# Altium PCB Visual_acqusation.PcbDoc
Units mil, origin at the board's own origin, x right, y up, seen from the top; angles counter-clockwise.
Board outline 1181.1 x 1968.5 mil, 2 copper layers (Top Layer, Bottom Layer), stack 65.792 mil thick; 39 components, 21 nets, 119 pads, 35 vias.
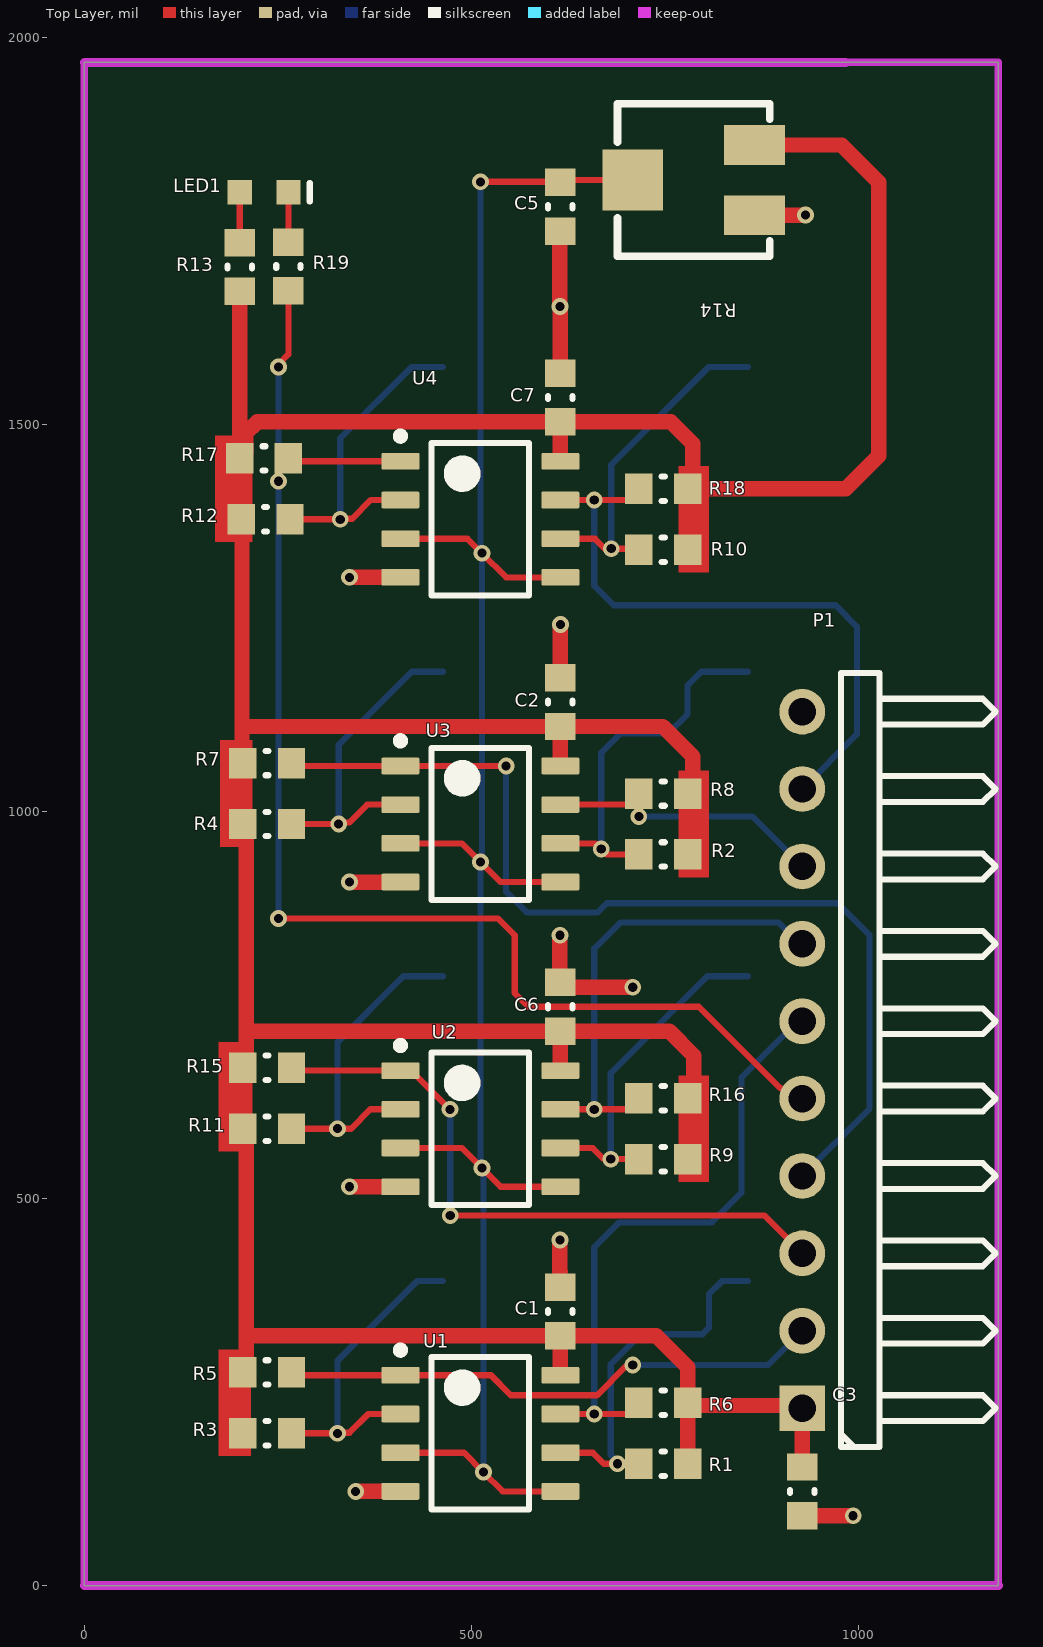
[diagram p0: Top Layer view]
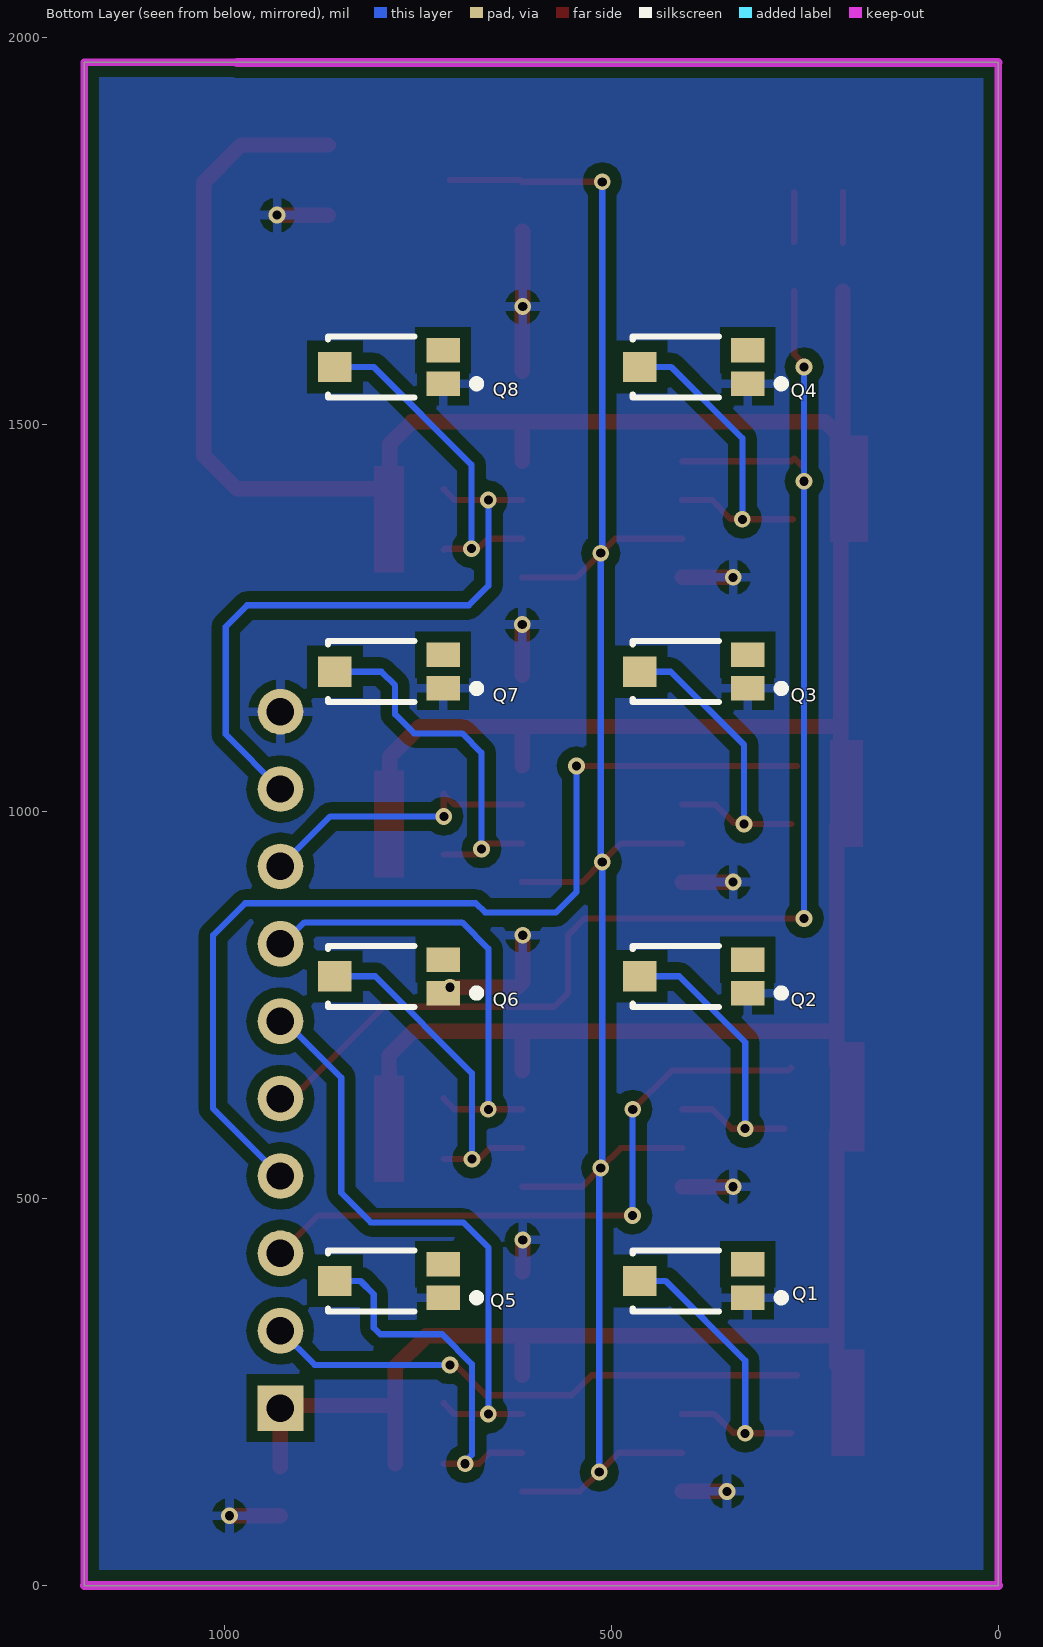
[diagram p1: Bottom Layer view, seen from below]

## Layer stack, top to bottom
Top Solder: solder mask 0.4, Solder Resist, Dk 3.5
Top Layer: signal copper 1.4
Dielectric1: core 62.9921, FR-4, Dk 4.8
Bottom Layer: signal copper 1.4
Bottom Solder: solder mask 0.4, Solder Resist, Dk 3.5

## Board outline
0,0 1181.1,0 1181.1,1968.5 0,1968.5

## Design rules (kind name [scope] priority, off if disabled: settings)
Clearance Clearance_1 [InPolygon] p1: gap=14 ignorepadtopadclearanceinfootprint=FALSE except(0: Arc-Hole Track-Hole SMDPad-Hole THPad-Hole Via-Hole Fill-Hole Poly-Hole Region-Hole Text-Hole)
Clearance [All] p2: gap=6 ignorepadtopadclearanceinfootprint=FALSE except(0: Arc-Hole Track-Hole SMDPad-Hole THPad-Hole Via-Hole Fill-Hole Poly-Hole Region-Hole Text-Hole)
FabricationTestPointUsage TestPointUsage [All] p1: valid=0 allowmultiple=FALSE
FabricationTestpoint Testpoint [(IsPad And (OnTopLayer Or OnBottomLayer))] p1: side=3 testpointundercomponent=TRUE minsize=40 maxsize=100 preferedsize=60 minholesize=0 maxholesize=40 preferedholesize=32 testpointgrid=1 allowsidetop=TRUE allowsidebottom=TRUE usegrid=TRUE gridtolerance=0.01
HoleSize [All] p1: absolutevalues=TRUE maxlimit=787.4 minlimit=11.81 maxpercent=80.000 minpercent=20.000
HoleToHoleClearance [All] p1: gap=0 allowstackedmicrovias=TRUE
MinimumSolderMaskSliver [All] p1: minsoldermaskwidth=0
PlaneClearance [All] p1: clearance=15.75
PlaneConnect [All] p1: planeconnectstyle=Direct reliefexpansion=11.81 reliefentries=4 reliefconductorwidth=11.81 reliefairgap=11.81
PolygonConnect [All] p1: connectstyle=Relief reliefconductorwidth=11.81 reliefentries=4 polygonreliefangle="90 Angle" airgapwidth=11.81
RoutingVias [All] p1: holewidth=19.68 width=51.18 viastyle="Through Hole" minholewidth=11.81 minwidth=19.68 maxholewidth=393.7 maxwidth=787.4
SilkToSilkClearance [All] p1: silktosilkclearance=0
SilkToSolderMaskClearance SilkscreenOverComponentPads [IsPad] p1: minsilkscreentomaskgap=0 clearancetoexposedcopper=TRUE
SolderMaskExpansion [All] p1: expansion=4 istentingtop=FALSE
Width [All] p1: maxlimit=200 minlimit=6 preferedwidth=10
21 further rules are at their usual default settings.

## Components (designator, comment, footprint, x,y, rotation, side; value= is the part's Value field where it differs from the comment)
C1 "CAP 100nF 6.3V" CAPC0603(1608)100_N 615.16,354.33 r270 top value=100nF
C2 "CAP 100nF 6.3V" CAPC0603(1608)100_N 615.16,1141.73 r270 top value=100nF
C3 "CAP 100nF 6.3V" CAPC0603(1608)100_N 927.68,121.85 r90 top value=100nF
C5 "CAP 100nF 6.3V" CAPC0603(1608)100_N 615.16,1781.96 r90 top value=100nF
C6 "CAP 100nF 6.3V" CAPC0603(1608)100_N 615.16,748.03 r270 top value=100nF
C7 "CAP 100nF 6.3V" CAPC0603(1608)100_N 615.16,1535.43 r270 top value=100nF
LED1 "150060BS75000" 0603_A 232.28,1800.66 r180 top
P1 "Header 10H" HDR1X10H 927.68,229.43 r90 top
Q1 "TEMT6000X01" VSIL-TEMT6000X01_V 393.7,393.7 r0 bottom locked
Q2 "TEMT6000X01" VSIL-TEMT6000X01_V 393.7,787.4 r0 bottom locked
Q3 "TEMT6000X01" VSIL-TEMT6000X01_V 393.7,1181.1 r0 bottom locked
Q4 "TEMT6000X01" VSIL-TEMT6000X01_V 393.7,1574.8 r0 bottom locked
Q5 "TEMT6000X01" VSIL-TEMT6000X01_V 787.4,393.7 r0 bottom locked
Q6 "TEMT6000X01" VSIL-TEMT6000X01_V 787.4,787.4 r0 bottom locked
Q7 "TEMT6000X01" VSIL-TEMT6000X01_V 787.4,1181.1 r0 bottom locked
Q8 "TEMT6000X01" VSIL-TEMT6000X01_V 787.4,1574.8 r0 bottom locked
R1 "10K 1% 0603(1608)" RESC0603(1608)_N 748.03,157.48 r0 top value="10000.00 Ohm"
R2 "10K 1% 0603(1608)" RESC0603(1608)_N 748.03,944.88 r0 top value="10000.00 Ohm"
R3 "10K 1% 0603(1608)" RESC0603(1608)_N 236.22,196.85 r180 top value="10000.00 Ohm"
R4 "10K 1% 0603(1608)" RESC0603(1608)_N 236.22,984.25 r180 top value="10000.00 Ohm"
R5 "1K 1% 0603(1608)" RESC0603(1608)_N 236.22,275.59 r180 top value="3300.00 Ohm"
R6 "3K3 1% 0603(1608)" RESC0603(1608)_N 748.03,236.22 r0 top value="3300.00 Ohm"
R7 "1K 1% 0603(1608)" RESC0603(1608)_N 236.22,1062.99 r180 top value="3300.00 Ohm"
R8 "3K3 1% 0603(1608)" RESC0603(1608)_N 748.03,1023.62 r0 top value="3300.00 Ohm"
R9 "10K 1% 0603(1608)" RESC0603(1608)_N 748.03,551.18 r0 top value="10000.00 Ohm"
R10 "10K 1% 0603(1608)" RESC0603(1608)_N 748.03,1338.58 r0 top value="10000.00 Ohm"
R11 "10K 1% 0603(1608)" RESC0603(1608)_N 236.22,590.55 r180 top value="10000.00 Ohm"
R12 "10K 1% 0603(1608)" RESC0603(1608)_N 234.25,1377.95 r180 top value="10000.00 Ohm"
R13 "1K 1%" RESC0603(1608)_N 200.79,1703.96 r270 top value="1000.00 Ohm"
R14 "RPot SM" POT4MM-2 787.4,1816.4 r180 top
R15 "1K 1% 0603(1608)" RESC0603(1608)_N 236.22,669.29 r180 top value="3300.00 Ohm"
R16 "3K3 1% 0603(1608)" RESC0603(1608)_N 748.03,629.92 r0 top value="3300.00 Ohm"
R17 "1K 1% 0603(1608)" RESC0603(1608)_N 232.28,1456.69 r180 top value="3300.00 Ohm"
R18 "3K3 1% 0603(1608)" RESC0603(1608)_N 748.03,1417.32 r0 top value="3300.00 Ohm"
R19 "0" RESC0603(1608)_N 263.78,1704.7 r90 top value="1000.00 Ohm"
U1 "LM393M" D0008A_L 511.81,196.85 r0 top
U2 "LM393M" D0008A_L 511.81,590.55 r0 top
U3 "LM393M" D0008A_L 511.81,984.25 r0 top
U4 "LM393M" D0008A_L 511.81,1377.95 r0 top

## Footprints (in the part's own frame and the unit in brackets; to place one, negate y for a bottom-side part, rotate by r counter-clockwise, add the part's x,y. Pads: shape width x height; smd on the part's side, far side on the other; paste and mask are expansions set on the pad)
0603_A [mm] "Chip LED, 2-Leads, Body 1.6x0.8mm, IPC Medium Density"
  rect 0.8x0.8 smd: 1(-0.8,0) 2(0.8,0)
  silkscreen extent -1.5,-0.3 -1.5,0.3, body extent -0.8,-0.4 0.8,0.4, height 0.7
CAPC0603(1608)100_N [mm] "Chip Capacitor, Body 1.6x0.8mm, Height 1.0mm, IPC Medium Density"
  rect 0.9x1 smd: 1(-0.8,0) 2(0.8,0)
  silkscreen extent -0.05,-0.4 0.05,0.4, body extent -0.87,-0.48 0.88,0.47, height 1
D0008A_L [mm] "SOIC, 8-Leads, Body 5x4mm, Pitch 1.27mm, IPC High Density"
  rrect18% 1.25x0.55 smd: 1(-2.625,1.905) 2(-2.625,0.635) 3(-2.625,-0.635) 4(-2.625,-1.905) 5(2.625,-1.905) 6(2.625,-0.635) 7(2.625,0.635) 8(2.625,1.905)
  silkscreen extent -2.75,-2.5 1.6,2.85, body extent -3,-2.45 3,2.45, height 1.63
HDR1X10H [mm] "Connector; Header; 10 Position; Right Angle"
  rect 1.5x1.5 hole 0.9: 1(0,0)
  round 1.5 hole 0.9: 2(2.54,0) 3(5.08,0) 4(7.62,0) 5(10.16,0) 6(12.7,0) 7(15.24,0) 8(17.78,0) 9(20.32,0) 10(22.86,0)
  silkscreen extent -1.27,-6.35 24.13,-1.27
POT4MM-2 [mm] "Square Trimming Potentiometer"
  rect 2x1.3 smd: CCW(-2,-1.15) CW(-2,1.15)
  rect 2x2 smd: W(2,0)
  silkscreen extent -2.5,-2.5 2.5,2.5
RESC0603(1608)_N [mm] "Chip Resistor, Body 1.6x0.8mm, IPC Medium Density"
  rect 0.9x1 smd: 1(-0.8,0) 2(0.8,0)
  silkscreen extent -0.05,-0.4 0.05,0.4, body extent -0.85,-0.47 0.85,0.47, height 0.6
VSIL-TEMT6000X01_V [mm] "SMD, 3-Leads, Body 4x2mm"
  rect 1.1x0.8 smd: 1(-1.775,0.55) 2(-1.775,-0.55)
  rect 1.1x1 smd: 3(1.775,0)
  silkscreen extent -3,-1 2,1, body extent -2,-1 2,1, height 1.05

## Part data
C1 C2 C3 C5 C6 C7: library part CMP-1035-02576-1, "CAP 100nF 6.3V ±10% 0603 (1608 Metric) Thickness 1mm SMD", Case-EIA=0603, Case-Metric=1608, Rated Voltage="6.3 V", Tolerance=Â±10%
LED1: library part CMP-1426-00003-1, "SMD mono-color Chip LED, WL-SMCW, Blue", Color=Blue, Manufacturer="Wuerth Elektronik"
P1: "Header, 10-Pin, Right Angle"
Q1 Q2 Q3 Q5 Q6 Q7 Q8: library part CMP-1666-00035-1, "Ambient Light Sensor / , 100 mW, -40 to 100 degC, 3-Pin SMD, RoHS, Tape and Reel", Case Code (Imperial)=0603, Case Code (Metric)=1608, Colour=Red, Forward Current="20 mA", Forward Voltage="2 V", Max Operating Temperature="85 degC", Min Operating Temperature="-55 degC", Package Quantity=3000, Power Rating="75 mW"
Q4: library part CMP-1666-00035-1, "Ambient Light Sensor / , 100 mW, -40 to 100 degC, 3-Pin SMD, RoHS, Tape and Reel", Case\Package=0603, Case Code (Metric)=1608, Colour=Red, Forward Current="20 mA", Forward Voltage="2 V", Max Operating Temperature="85 degC", Min Operating Temperature="-55 degC", Package Quantity=3000, Power Rating="75 mW"
R1 R2 R3 R4 R9 R10 R11 R12: library part CMP-1012-00623-1, "10K 0.1W 1% 0603 (1608 Metric)  SMD", Case-EIA=0603, Case-Metric=1608, Power="0.1 W", Tolerance="1 %"
R5 R6 R7 R8 R15 R16 R17 R18: library part CMP-1012-00567-1, "3K3 0.1W 1% 0603 (1608 Metric)  SMD", Case-EIA=0603, Case-Metric=1608, Power="0.1 W", Tolerance="1 %"
R13 R19: library part CMP-1012-00510-1, "1K 0.1W 1% 0603 (1608 Metric)  SMD", Case-EIA=0603, Case-Metric=1608, Power="0.1 W", Tolerance="1 %"
R14: "Square Trimming Potentiometer"
U1 U2 U3 U4: library part CMP-0055-00682-3, "Low Power Low Offset Voltage Dual Comparator, 8-pin Narrow SOIC", Manufacturer="Texas Instruments", Package Reference=D0008A, PackageTopMarking=NSZXTT*LM*393M, PowerWise=N

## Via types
v1: diameter 21.65, hole 11.81, Top Layer to Bottom Layer, tented both sides, 35 vias

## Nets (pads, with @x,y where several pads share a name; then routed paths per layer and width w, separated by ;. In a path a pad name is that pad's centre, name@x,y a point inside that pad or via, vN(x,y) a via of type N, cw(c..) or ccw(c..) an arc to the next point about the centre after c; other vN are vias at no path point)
+5: C1.2 C2.2 C3.2 C6.2 C7.2 P1.1 R1.2 R2.2 R3.2 R4.2 R5.2 R6.2 R7.2 R8.2 R9.2 R10.2 R11.2 R12.2 R13.2 R14.CCW R15.2 R16.2 R17.2 R18.2 U1.8 U2.8 U3.8 U4.8 | length 5107.4
  Top Layer w20: R13.2 R17.2 208.4,1464.3 208.4,1488.91 223.43,1503.94 C7.2 757.88,1503.94 786.42,1475.39 786.42,1424.22 R18.2 983.85,1417.32 1026.77,1460.25 1026.77,1813.45 978.54,1861.68 R14.CCW ; R12.2 203.74,1376.97 203.74,1110.24 ; R5.2 197.01,283.31 207.06,283.31 209.02,285.28 209.02,322.83 ; R11.2 209.02,586.25 209.02,322.83 ; R15.2 209.02,673.59 209.02,716.54 ; R4.2 209.02,979.95 209.02,716.54 ; R7.2 203.74,1063.98 203.74,1110.24 ; U1.8 C1.2 ; U2.8 C6.2 ; U3.8 C2.2 ; U4.8 C7.2@615.16,1496.06 ; R1.2 R6.2 ; R16.2 787.24,637.64 787.24,668.31 787.4,668.47 787.4,685.04 755.91,716.54 C6.2 ; R8.2 787.4,1031.5 786.42,1032.48 786.42,1071.43 747.62,1110.24 C2.2 ; C3.2 P1.1 924.28,232.82 782.92,232.82 R6.2 ; 203.74,1110.24 C2.2 ; 209.02,322.83 C1.2 ; 209.02,716.54 C6.2 ; C1.2 739.17,322.83 779.53,282.48 R6.2
GND: C1.1 C2.1 C3.1 C5.1 C6.1 C7.1 P1.10 Q1.1 Q2.1 Q3.1 Q4.1 Q5.1 Q6.1 Q7.1 Q8.1 R14.CW U1.4 U2.4 U3.4 U4.4 | length 833
  Top Layer w20: v1(342.64,515.55) U2.4 ; v1(342.64,909.25) U3.4 ; v1(342.64,1302.95) U4.4 ; v1(350.59,121.85) U1.4 ; v1(614.54,446.83) 614.54,406.13 615.16,405.51 ; v1(614.54,840.44) 614.54,780.14 621.35,773.33 v1(708.66,773.33) ; C2.1@615.16,1176.18 v1(615.16,1242) ; C7.1@615.16,1569.57 615.16,1651.85 614.54,1652.47 614.54,1749.84 C5.1 ; R14.CW v1(931.96,1771.13) ; C3.1 v1(993.5,90.35)
  other v1: 614.54,1652.91
LED: P1.5 R17.1 R19.1 U4.1 | length 1814.2
  Top Layer w8: v1(250.98,862.24) 534.29,862.24 556.1,840.44 556.1,765.75 573.82,748.03 794.07,748.03 898.81,643.29 900,643.29 913.86,629.43 P1.5 ; v1(250.98,1427.17) 250.98,1443.9 R17.1 267.52,1452.95 U4.1 ; v1(250.98,1574.8) 250.98,1578.5 263.78,1591.29 R19.1
  Bottom Layer w8: v1(250.98,862.24) v1(250.98,1427.17) v1(250.98,1574.8)
NetC5_2: C5.2 R14.W U1.3 U1.5 U2.3 U2.5 U3.3 U3.5 U4.3 U4.5 | length 2778.5
  Top Layer w8: U1.3 490.74,171.85 v1(515.74,146.85) 540.74,121.85 U1.5 ; U2.3 488.19,565.55 513.77,539.97 v1(513.77,539.74) 537.97,515.55 U2.5 ; U3.3 487.81,959.25 v1(511.81,935.25) 537.81,909.25 U3.5 ; U4.3 495.07,1352.95 v1(513.77,1334.25) 545.07,1302.95 U4.5 ; v1(511.81,1814.07) 614.54,1814.07 C5.2 618.11,1816.4 R14.W
  Bottom Layer w8: v1(511.81,1814.07) 511.81,1336.21 v1(513.77,1334.25) 513.77,937.21 v1(511.81,935.25) 511.81,541.71 v1(513.77,539.74) 515.74,537.78 v1(515.74,146.85)
NetLED1_1: LED1.1 R19.2 | length 64.5
  Top Layer w8: R19.2 LED1.1
NetLED1_2: LED1.2 R13.1 | length 65.2
  Top Layer w8: R13.1 LED1.2
NetP1_2: P1.2 R5.1 U1.1 | length 712.6
  Top Layer w8: R5.1@260.34,271.85 U1.1 525.5,271.85 551.29,246.06 662.53,246.06 701.74,285.28 v1(708.66,285.28)
  Bottom Layer w8: v1(708.66,285.28) 883.52,285.28 P1.2
NetP1_3: P1.3 R15.1 U2.1 | length 839.4
  Top Layer w8: R15.1 271.46,665.55 U2.1 422.24,665.55 472.24,615.55 v1(472.44,615.55) ; v1(472.79,478.51) 878.6,478.51 P1.3
  Bottom Layer w8: v1(472.44,615.55) 472.79,615.2 v1(472.79,478.51)
NetP1_4: P1.4 R7.1 U3.1 | length 1297.2
  Top Layer w8: R7.1@260.44,1059.25 U3.1 v1(545.07,1059.25)
  Bottom Layer w8: v1(545.07,1059.25) 545.07,896.49 571.54,870.02 663.33,870.02 675.2,881.89 973.3,881.89 1014.75,840.44 1014.75,616.51 P1.4
NetP1_6: P1.6 R6.1 U1.7 | length 800
  Top Layer w8: U1.7 v1(658.99,221.85) 702.82,221.85 716.54,235.57 R6.1
  Bottom Layer w8: v1(658.99,221.85) 658.99,437.06 691.4,469.48 811.01,469.48 849.19,507.66 849.19,656.64 921.98,729.43 P1.6
NetP1_7: P1.7 R16.1 U2.7 | length 609.6
  Top Layer w8: U2.7 v1(658.99,615.55) 702.82,615.55 716.54,629.27 R16.1
  Bottom Layer w8: v1(658.99,615.55) 658.99,823.19 692.91,857.12 896.64,857.12 924.33,829.43 P1.7
NetP1_8: P1.8 R8.1 U3.7 | length 374.5
  Top Layer w8: U3.7 702.82,1009.25 R8.1@716.54,1022.97 ; v1(716.54,994.09) R8.1@716.54,1022.97 ; R8.1 R8.1@716.54,1022.97
  Bottom Layer w8: v1(716.54,994.09) 863.01,994.09 P1.8
NetP1_9: P1.9 R18.1 U4.7 | length 819
  Top Layer w8: U4.7 v1(658.99,1402.95) 702.82,1402.95 716.54,1416.67 R18.1
  Bottom Layer w8: v1(658.99,1402.95) 658.99,1292.03 684.21,1266.81 970.76,1266.81 998.4,1239.16 998.4,1100.16 P1.9
NetQ1_3: Q1.3 R3.1 U1.2 | length 424.1
  Top Layer w8: R3.1 v1(327.16,196.85) 327.96,197.65 342.64,197.65 366.85,221.85 U1.2
  Bottom Layer w8: v1(327.16,196.85) 327.16,290.86 430,393.7 Q1.3
NetQ2_3: Q2.3 R11.1 U2.2 | length 425.7
  Top Layer w8: R11.1@276.51,590.55 344.68,590.55 369.68,615.55 U2.2
  Bottom Layer w8: v1(327.16,590.55) 327.16,702.28 412.28,787.4 Q2.3
NetQ3_3: Q3.3 R4.1 U3.2 | length 427.5
  Top Layer w8: R4.1 v1(328.67,984.25) 330.78,986.37 342.83,986.37 365.72,1009.25 U3.2
  Bottom Layer w8: v1(328.67,984.25) 328.67,1086.54 423.23,1181.1 Q3.3
NetQ4_3: Q4.3 R12.1 U4.2 | length 428.8
  Top Layer w8: R12.1 v1(330.78,1377.95) 331.64,1378.81 346.21,1378.81 370.35,1402.95 U4.2
  Bottom Layer w8: v1(330.78,1377.95) 330.78,1482.75 422.83,1574.8 Q4.3
NetQ5_3: Q5.3 R1.1 U1.6 | length 486.7
  Top Layer w8: U1.6 657.12,171.85 671.49,157.48 R1.1
  Bottom Layer w8: v1(688.98,157.48) 688.98,160.25 680.23,168.99 680.23,286.3 718.74,324.8 798.76,324.8 807.07,333.12 807.07,376.53 824.24,393.7 Q5.3
NetQ6_3: Q6.3 R9.1 U2.6 | length 447.4
  Top Layer w8: U2.6 657.12,565.55 671.49,551.18 v1(680.23,551.18) R9.1
  Bottom Layer w8: v1(680.23,551.18) 680.23,662.45 805.18,787.4 Q6.3
NetQ7_3: Q7.3 R2.1 U3.6 | length 486.2
  Top Layer w8: U3.6 660.71,959.25 675.08,944.88 R2.1
  Bottom Layer w8: v1(667.9,952.07) 667.9,1076.36 692.91,1101.38 754.8,1101.38 779.53,1126.1 779.53,1163.39 797.24,1181.1 Q7.3
NetQ8_3: Q8.3 R10.1 U4.6 | length 444.6
  Top Layer w8: U4.6 659.84,1352.95 672.76,1340.04 v1(680.87,1340.04) 715.08,1340.04 R10.1
  Bottom Layer w8: v1(680.87,1340.04) 680.87,1448.58 807.09,1574.8 Q8.3
pads on no net: Q1.2 Q2.2 Q3.2 Q4.2 Q5.2 Q6.2 Q7.2 Q8.2

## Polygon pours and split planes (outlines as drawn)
no net on Top Layer "NONET_L01_P004" (solid, pour order 4): 763.78,241.14
no net on Top Layer "Top Layer-No Net" (solid, pour order 0): 544.17,-886.5
GND on Bottom Layer "Bottom Layer-No Net" (solid, pour order 2): 0,0 1181.1,0 1181.1,1968.5 0,1968.5

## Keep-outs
Keep-Out Layer:
  lines w10: 0,0 0,1968.5 1181.1,1968.5 1181.1,0
  lines w11.81: 0,0 1181.1,0 ; 0.57,1968.5 983.85,1968.5

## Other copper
Top Layer:
  rectangle net +5: 767.72,521.65 807.09,659.45
  rectangle net +5: 767.72,915.35 807.09,1053.15
  rectangle net +5: 767.72,1309.06 807.09,1446.85
  rectangle net +5: 168.71,1348.43 217.52,1486.22
  rectangle net +5: 175.2,954.72 217.52,1092.52
  rectangle net +5: 173.23,167.32 215.55,305.12
  rectangle net +5: 173.23,561.02 217.52,702.28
